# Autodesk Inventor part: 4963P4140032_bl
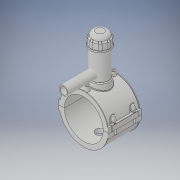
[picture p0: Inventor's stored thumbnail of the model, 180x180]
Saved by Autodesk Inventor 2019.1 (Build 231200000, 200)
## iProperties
Created: 2017-07
Part Number: 4963P4140032_bl
Material: Generic
Document SubType Name: Modeling
Designer: KIM
Density: 1 g/cm^3
Appearance: Default
Author: KIM
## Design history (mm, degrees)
derived "4963P4.ipt"
feature "Solid1::4963P4.ipt" dims "ScaleForDerivedMember" = 10
feature "Solid2::4963P4.ipt" dims "ScaleForDerivedMember" = 10
feature "Solid3::4963P4.ipt" dims "ScaleForDerivedMember" = 10
tag "TaggingFeature1"
body "Solid1"
body "Solid2"
body "Solid3"
other parameters: "d3" = 35 [user parameter], "d4" = 118 [user parameter], "d5" = 0 [user parameter], "d6" = 0.1 [user parameter], "d8" = 0 [user parameter], "d19" = 6 [user parameter], "d20" = 6 [user parameter], "d21" = 70.8 [user parameter], "d23" = 0 [user parameter], "d24" = 35.4 [user parameter], "d26" = 0 [user parameter], "d27" = 3 [user parameter], "d28" = 3 [user parameter], "d29" = 3 [user parameter], "d30" = 46.66667 [user parameter], "d31" = 6 [user parameter], "d32" = 0 [user parameter], "d33" = 0 [user parameter], "d34" = 0.6 [user parameter], "d40" = 88.816 [user parameter], "d43" = 0 [user parameter], "d45" = 0 [user parameter], "d47" = 156.2 [user parameter], "d70" = 15 [user parameter], "d72" = 0 [user parameter], "d73" = 6 [user parameter], "d75" = 5 [user parameter], "d76" = 0 [user parameter], "d77" = 7 [user parameter], "d79" = 15 [user parameter], "d80" = 47.2 [user parameter], "d82" = 5 deg [user parameter], "d84" = 4 [user parameter], "d85" = 14 [user parameter], "d86" = 0 [user parameter], "d87" = 3 [user parameter], "d88" = 0 [user parameter], "d89" = 1 [user parameter], "d90" = 1 [user parameter], "d91" = 94.4 [user parameter], "d92" = 0 [user parameter], "d93" = 0.5 [user parameter], "d94" = 73.68421 [user parameter], "d96" = 174.216 [user parameter], "d97" = 2.36 [user parameter], "d98" = 0 [user parameter], "d102" = 1.4 [user parameter], "d120" = 140 deg [user parameter], "d121" = 24.228 [user parameter], "d122" = 20 deg [user parameter], "d123" = 341.6 [user parameter], "d124" = 102.48 [user parameter], "d126" = 0 [user parameter], "d143" = 144.2 [user parameter], "d145" = 23.69231 [user parameter], "d149" = 2.1 [user parameter], "d150" = 26.06154 [user parameter], "d153" = 118 [user parameter], "d154" = 0 [user parameter], "d156" = 85.4 [user parameter], "d157" = 160 deg [user parameter], "d159" = 6.16 [user parameter], "d161" = 2.1 [user parameter], "d162" = 70.8 [user parameter], "d163" = 0 [user parameter], "d167" = 14 [user parameter], "d168" = 83.31707 [user parameter], "d170" = 3.75 [user parameter], "d172" = 0 [user parameter], "d173" = 1 [user parameter], "d176" = 20 deg [user parameter], "d177" = 9.8 [user parameter], "d178" = 30.8 [user parameter], "d180" = 0 [user parameter], "d183" = 12.32 [user parameter], "d184" = 7.84 [user parameter], "d185" = 38.35 [user parameter], "d186" = 38.35 [user parameter], "d187" = 85.4 [user parameter], "d188" = 9.24 [user parameter], "d189" = 9.8 [user parameter], "d190" = 0 [user parameter], "d191" = 128.1 [user parameter], "d193" = 8 [user parameter], "d194" = 4.13 [user parameter], "d195" = 90 deg [user parameter], "d197" = 0 [user parameter], "d199" = 0 [user parameter], "d200" = 15.4 [user parameter], "d202" = 0 [user parameter], "d203" = 177 [user parameter], "d204" = 66.5 [user parameter], "d205" = 49 [user parameter], "d206" = 59.5 [user parameter], "d207" = 132.75 [user parameter], "d208" = 138.06 [user parameter], "d209" = 164.61 [user parameter], "d210" = 60.2 [user parameter], "d212" = 56 [user parameter], "d213" = 36 [user parameter], "d216" = 0 [user parameter], "d217" = 14 [user parameter], "d218" = 14 [user parameter], "d219" = 2.8 [user parameter], "d224" = 0 [user parameter], "d225" = 56 [user parameter], "d226" = 32 [user parameter], "d227" = 25.6 [user parameter], "d228" = 132 [user parameter], "d230" = 5.6 [user parameter], "L_" = 118 [user parameter], "d_t" = 6 [user parameter], "H_2" = 177 [user parameter], "H_1" = 56 [user parameter], "d_1" = 32 [user parameter], "H_" = 132 [user parameter], "d1" = 170.8 [user parameter], "d148" = 2.1 [user parameter], "d160" = 2.1 [user parameter], "d169" = 3.75 [user parameter]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
